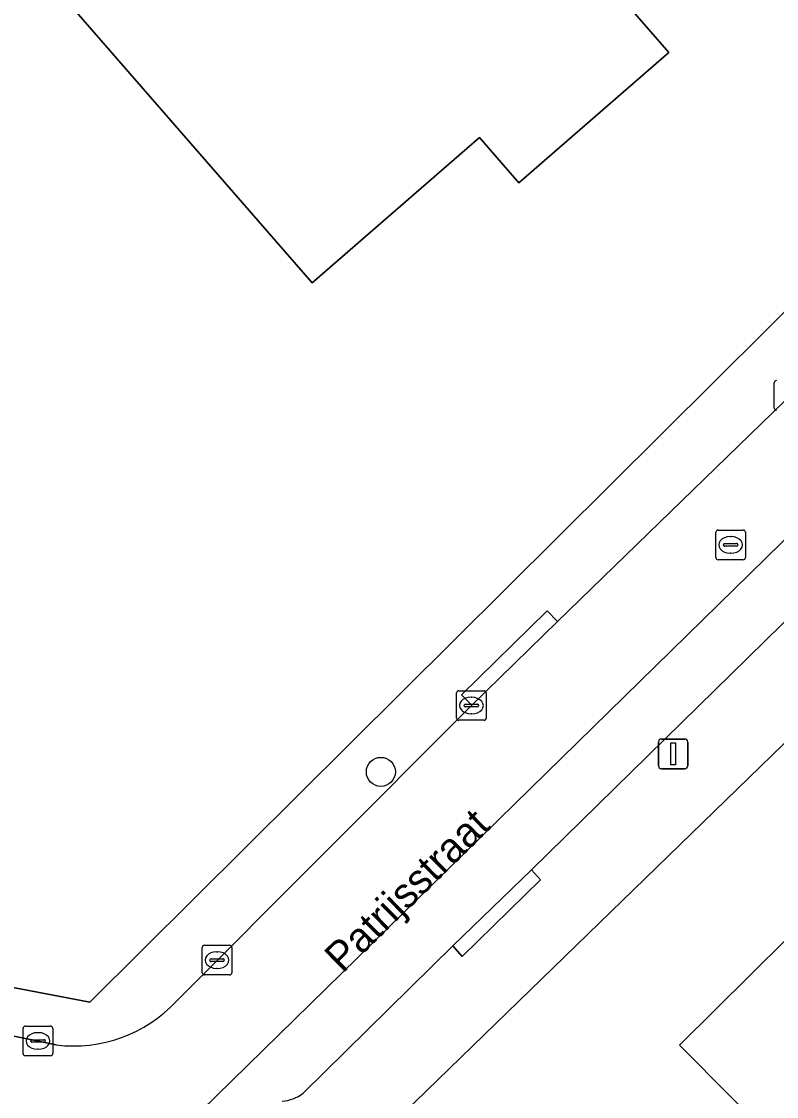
# Model space of a CAD drawing. Extents: x 161772 to 163126, y 383092 to 383917.
# Drawn here: x 162030.56 to 162056.01, y 383362.12 to 383398.39 of the extents above; entities that cross this region are included whole.
import ezdxf

# ---------------------------------------------------------------- set-up
doc = ezdxf.new("R2010")
doc.units = 0
for name, color, linetype in [('IMGEO_Boom', 7, 'Continuous'), ('IMGEO_Erf', 7, 'Continuous'), ('IMGEO_Kolk', 7, 'Continuous'), ('IMGEO_Lichtmast', 7, 'Continuous'), ('IMGEO_Openbare_ruimte_label', 7, 'Continuous'), ('IMGEO_Pand', 7, 'Continuous'), ('IMGEO_Parkeervlak_open', 7, 'Continuous'), ('IMGEO_Rijbaan_lokaal_open', 7, 'Continuous'), ('IMGEO_Rioolput', 7, 'Continuous'), ('IMGEO_Voetpad_gesloten', 7, 'Continuous'), ('IMGEO_Voetpad_open', 7, 'Continuous')]:
    doc.layers.add(name, color=color, linetype=linetype)

msp = doc.modelspace()

# ---------------------------------------------------------------- linework, layer by layer
at = {"layer": 'IMGEO_Boom'}
msp.add_circle((162042.673, 383373.072), 0.489, dxfattribs=at)
at = {"layer": 'IMGEO_Erf'}
for points in [[(161988.831, 383383.094), (161989.798, 383375.666), (161990.795, 383374.566), (161992.579, 383373.341), (161993.75, 383372.87), (162001.33, 383371.327), (162032.857, 383365.301), (162067.97, 383400.221), (162013.474, 383465.049)], [(162056.238, 383360.337), (162052.746, 383363.85), (162057.56, 383368.632)]]:
    msp.add_lwpolyline(points, dxfattribs=at)
for points in [[(162042.442, 383413.304), (162046.279, 383416.509), (162052.35, 383409.242), (162051.959, 383408.915), (162054.742, 383405.585), (162050.598, 383402.122), (162051.674, 383400.885), (162050.321, 383399.709), (162052.378, 383397.343), (162047.321, 383392.948), (162046.001, 383394.468), (162040.357, 383389.564), (162031.415, 383399.854), (162035.794, 383403.659), (162038.856, 383400.136), (162044.666, 383405.185), (162039.757, 383411.061)], [(162085.05, 383335.095), (162085.636, 383334.487), (162109.459, 383358.96), (162108.772, 383359.637), (162097.704, 383370.546), (162075.222, 383392.703), (162064.395, 383381.925), (162038.775, 383357.03), (162035.617, 383357.251), (162035.13, 383353.454), (162066.087, 383323.385), (162066.709, 383324.02), (162059.456, 383331.069), (162065.31, 383337.087), (162065.453, 383336.949), (162072.586, 383330.051), (162076.509, 383326.257)]]:
    msp.add_lwpolyline(points, close=True, dxfattribs=at)
at = {"layer": 'IMGEO_Kolk'}
for p, q in [((162055.936, 383385.344), (162055.936, 383386.196)), ((162045.227, 383374.884), (162045.227, 383375.736)), ((162045.302, 383375.81), (162046.154, 383375.81)), ((162045.715, 383375.59), (162045.74, 383375.59)), ((162046.228, 383375.736), (162046.228, 383374.884)), ((162045.486, 383375.304), (162045.486, 383375.316)), ((162045.924, 383375.267), (162045.526, 383375.267)), ((162045.529, 383375.353), (162045.927, 383375.353)), ((162045.97, 383375.316), (162045.97, 383375.304)), ((162046.154, 383374.81), (162045.302, 383374.81)), ((162045.738, 383375.03), (162045.713, 383375.03)), ((162036.723, 383367.22), (162037.575, 383367.22)), ((162036.648, 383366.294), (162036.648, 383367.146)), ((162037.136, 383367), (162037.161, 383367)), ((162037.649, 383367.146), (162037.649, 383366.294)), ((162036.907, 383366.714), (162036.907, 383366.726)), ((162037.345, 383366.677), (162036.947, 383366.677)), ((162036.95, 383366.763), (162037.348, 383366.763)), ((162037.391, 383366.726), (162037.391, 383366.714)), ((162037.575, 383366.22), (162036.723, 383366.22)), ((162037.159, 383366.44), (162037.134, 383366.44)), ((162030.612, 383363.567), (162030.612, 383364.419)), ((162030.687, 383364.493), (162031.539, 383364.493)), ((162031.613, 383364.419), (162031.613, 383363.567)), ((162030.871, 383363.987), (162030.871, 383363.999)), ((162031.309, 383363.95), (162030.911, 383363.95)), ((162030.914, 383364.036), (162031.312, 383364.036)), ((162031.1, 383364.273), (162031.125, 383364.273)), ((162031.355, 383363.999), (162031.355, 383363.987)), ((162031.123, 383363.713), (162031.098, 383363.713)), ((162031.539, 383363.493), (162030.687, 383363.493))]:
    msp.add_line(p, q, dxfattribs=at)
for points in [[(162055.936, 383385.344), (162055.936, 383386.196)], [(162045.227, 383374.884), (162045.227, 383375.736)], [(162045.302, 383375.81), (162046.154, 383375.81)], [(162046.228, 383375.736), (162046.228, 383374.884)], [(162046.154, 383374.81), (162045.302, 383374.81)], [(162036.723, 383367.22), (162037.575, 383367.22)], [(162036.648, 383366.294), (162036.648, 383367.146)], [(162037.649, 383367.146), (162037.649, 383366.294)], [(162037.575, 383366.22), (162036.723, 383366.22)], [(162030.612, 383363.567), (162030.612, 383364.419)], [(162030.687, 383364.493), (162031.539, 383364.493)], [(162031.613, 383364.419), (162031.613, 383363.567)], [(162031.539, 383363.493), (162030.687, 383363.493)]]:
    msp.add_lwpolyline(points, dxfattribs=at)
for centre, radius, start, end in [((162056.013, 383386.194), 0.0765, 91.552, 178.448), ((162056.013, 383386.194), 0.0765, 91.552, 178.448), ((162056.013, 383385.346), 0.0765, 181.552, 268.448), ((162056.013, 383385.346), 0.0765, 181.552, 268.448), ((162045.304, 383375.734), 0.0765, 91.552, 178.448), ((162045.304, 383375.734), 0.0765, 91.552, 178.448), ((162046.152, 383375.734), 0.0765, 1.552, 88.448), ((162046.152, 383375.734), 0.0765, 1.552, 88.448), ((162045.526, 383375.313), 0.0403, 85.8775, 175.7526), ((162045.523, 383375.303), 0.0366, 178.938, 274.7102), ((162045.927, 383375.31), 0.043, 264.8664, 352.4533), ((162045.931, 383375.315), 0.0386, 1.7309, 96.639), ((162045.304, 383374.886), 0.0765, 181.552, 268.448), ((162045.304, 383374.886), 0.0765, 181.552, 268.448), ((162046.152, 383374.886), 0.0765, 271.552, 358.448), ((162046.152, 383374.886), 0.0765, 271.552, 358.448), ((162036.725, 383367.144), 0.0765, 91.552, 178.448), ((162036.725, 383367.144), 0.0765, 91.552, 178.448), ((162037.573, 383367.144), 0.0765, 1.552, 88.448), ((162037.573, 383367.144), 0.0765, 1.552, 88.448), ((162036.947, 383366.723), 0.0403, 85.8775, 175.7526), ((162036.944, 383366.713), 0.0366, 178.938, 274.7102), ((162037.348, 383366.72), 0.043, 264.8664, 352.4533), ((162037.352, 383366.725), 0.0386, 1.7309, 96.639), ((162036.725, 383366.296), 0.0765, 181.552, 268.448), ((162036.725, 383366.296), 0.0765, 181.552, 268.448), ((162037.573, 383366.296), 0.0765, 271.552, 358.448), ((162037.573, 383366.296), 0.0765, 271.552, 358.448), ((162030.689, 383364.417), 0.0765, 91.552, 178.448), ((162030.689, 383364.417), 0.0765, 91.552, 178.448), ((162031.537, 383364.417), 0.0765, 1.552, 88.448), ((162031.537, 383364.417), 0.0765, 1.552, 88.448), ((162030.911, 383363.996), 0.0403, 85.8775, 175.7526), ((162030.908, 383363.986), 0.0366, 178.938, 274.7102), ((162031.312, 383363.993), 0.043, 264.8664, 352.4533), ((162031.316, 383363.998), 0.0386, 1.7309, 96.639), ((162030.689, 383363.569), 0.0765, 181.552, 268.448), ((162030.689, 383363.569), 0.0765, 181.552, 268.448), ((162031.537, 383363.569), 0.0765, 271.552, 358.448), ((162031.537, 383363.569), 0.0765, 271.552, 358.448)]:
    msp.add_arc(centre, radius, start, end, dxfattribs=at)
for centre, major_axis, ratio, start_param, end_param in [((162045.714, 383375.31), (-0.387, 0.002), 0.722429, 4.712389, 7.853982), ((162045.739, 383375.31), (-0.39, 0.002), 0.717154, 1.570796, 4.712389), ((162037.135, 383366.72), (-0.387, 0.002), 0.722429, 4.712389, 7.853982), ((162037.16, 383366.72), (-0.39, 0.002), 0.717154, 1.570796, 4.712389), ((162031.099, 383363.993), (-0.387, 0.002), 0.722429, 4.712389, 7.853982), ((162031.124, 383363.993), (-0.39, 0.002), 0.717154, 1.570796, 4.712389)]:
    msp.add_ellipse(centre, major_axis=major_axis, ratio=ratio, start_param=start_param, end_param=end_param, dxfattribs=at)
at = {"layer": 'IMGEO_Lichtmast'}
for p, q in [((162052.131, 383374.178), (162052.921, 383374.178)), ((162052.921, 383374.178), (162052.131, 383374.178)), ((162052.031, 383373.278), (162052.031, 383374.078)), ((162052.031, 383374.078), (162052.031, 383373.278)), ((162053.021, 383374.078), (162053.021, 383373.278)), ((162053.021, 383373.278), (162053.021, 383374.078)), ((162052.921, 383373.178), (162052.131, 383373.178)), ((162052.131, 383373.178), (162052.921, 383373.178))]:
    msp.add_line(p, q, dxfattribs=at)
msp.add_lwpolyline([(162052.451, 383374.053), (162052.601, 383374.053), (162052.601, 383373.303), (162052.451, 383373.303), (162052.451, 383374.053)], dxfattribs=at)
for centre, start, end in [((162052.131, 383374.078), 90, 180), ((162052.131, 383374.078), 90, 180), ((162052.921, 383374.078), 0, 90), ((162052.921, 383374.078), 360, 90), ((162052.131, 383373.278), 180, 270), ((162052.131, 383373.278), 180, 270), ((162052.921, 383373.278), 270, 0), ((162052.921, 383373.278), 270, 0)]:
    msp.add_arc(centre, 0.1, start, end, dxfattribs=at)
at = {"layer": 'IMGEO_Pand'}
for points in [[(162044.666, 383405.185), (162038.856, 383400.136), (162035.794, 383403.659), (162031.415, 383399.854), (162040.357, 383389.564), (162046.001, 383394.468), (162047.321, 383392.948), (162052.378, 383397.343), (162050.321, 383399.709), (162051.674, 383400.885), (162050.598, 383402.122), (162054.742, 383405.585), (162051.959, 383408.915), (162052.35, 383409.242), (162046.279, 383416.509), (162042.442, 383413.304), (162039.757, 383411.061)], [(162057.56, 383368.632), (162052.746, 383363.85), (162056.238, 383360.337), (162058.387, 383358.173), (162060.32, 383356.227), (162065.147, 383361.021)]]:
    msp.add_lwpolyline(points, close=True, dxfattribs=at)
at = {"layer": 'IMGEO_Parkeervlak_open'}
for points in [[(162069.402, 383393.751), (162036.595, 383361.608)], [(162040.056, 383362.229), (162045.1, 383367.2), (162047.756, 383369.771), (162068.538, 383390.157)]]:
    msp.add_lwpolyline(points, dxfattribs=at)
msp.add_arc((162039.229, 383363.336), 1.382, 274.7736, 306.7612, dxfattribs=at)
at = {"layer": 'IMGEO_Rijbaan_lokaal_open'}
for points in [[(162070.285, 383399.377), (162069.956, 383398.861), (162069.608, 383398.523), (162048.631, 383378.141), (162045.739, 383375.318), (162035.775, 383365.33)], [(162036.245, 383361.319), (162036.595, 383361.608), (162069.402, 383393.751)], [(162031.731, 383363.861), (162026.624, 383364.907), (162022.901, 383365.67), (161995.201, 383371.459), (161994.524, 383368.077), (162031.651, 383360.514), (162032.009, 383360.453)]]:
    msp.add_lwpolyline(points, dxfattribs=at)
msp.add_arc((162032.317, 383368.548), 4.724, 262.8729, 317.0546, dxfattribs=at)
at = {"layer": 'IMGEO_Rioolput'}
for p, q in [((162053.965, 383380.303), (162053.965, 383381.155)), ((162054.04, 383381.229), (162054.892, 383381.229)), ((162054.453, 383381.009), (162054.478, 383381.009)), ((162054.966, 383381.155), (162054.966, 383380.303)), ((162054.224, 383380.723), (162054.224, 383380.735)), ((162054.662, 383380.686), (162054.264, 383380.686)), ((162054.267, 383380.772), (162054.665, 383380.772)), ((162054.708, 383380.735), (162054.708, 383380.723)), ((162054.476, 383380.449), (162054.451, 383380.449)), ((162054.892, 383380.229), (162054.04, 383380.229))]:
    msp.add_line(p, q, dxfattribs=at)
for points in [[(162053.965, 383380.303), (162053.965, 383381.155)], [(162054.04, 383381.229), (162054.892, 383381.229)], [(162054.966, 383381.155), (162054.966, 383380.303)], [(162054.892, 383380.229), (162054.04, 383380.229)]]:
    msp.add_lwpolyline(points, dxfattribs=at)
for centre, radius, start, end in [((162054.042, 383381.153), 0.0765, 91.552, 178.448), ((162054.042, 383381.153), 0.0765, 91.552, 178.448), ((162054.89, 383381.153), 0.0765, 1.552, 88.448), ((162054.89, 383381.153), 0.0765, 1.552, 88.448), ((162054.264, 383380.732), 0.0403, 85.8775, 175.7526), ((162054.261, 383380.722), 0.0366, 178.938, 274.7102), ((162054.665, 383380.729), 0.043, 264.8664, 352.4533), ((162054.669, 383380.734), 0.0386, 1.7309, 96.639), ((162054.042, 383380.305), 0.0765, 181.552, 268.448), ((162054.042, 383380.305), 0.0765, 181.552, 268.448), ((162054.89, 383380.305), 0.0765, 271.552, 358.448), ((162054.89, 383380.305), 0.0765, 271.552, 358.448)]:
    msp.add_arc(centre, radius, start, end, dxfattribs=at)
for centre, major_axis, ratio, start_param, end_param in [((162054.452, 383380.729), (-0.387, 0.002), 0.722429, 4.712389, 7.853982), ((162054.477, 383380.729), (-0.39, 0.002), 0.717154, 1.570796, 4.712389)]:
    msp.add_ellipse(centre, major_axis=major_axis, ratio=ratio, start_param=start_param, end_param=end_param, dxfattribs=at)
at = {"layer": 'IMGEO_Voetpad_gesloten'}
for points in [[(162069.608, 383398.523), (162067.97, 383400.221), (162032.857, 383365.301), (162001.33, 383371.327), (161993.75, 383372.87), (161992.579, 383373.341), (161990.795, 383374.566), (161989.798, 383375.666), (161989.716, 383372.599), (161995.201, 383371.459), (162022.901, 383365.67), (162023.012, 383366.206), (162026.732, 383365.428), (162026.624, 383364.907), (162031.731, 383363.861)], [(162035.775, 383365.33), (162045.739, 383375.318), (162045.39, 383375.675), (162048.278, 383378.502), (162048.631, 383378.141), (162069.608, 383398.523)], [(162068.538, 383390.157), (162047.756, 383369.771), (162048.059, 383369.433), (162045.418, 383366.844), (162045.1, 383367.2), (162040.056, 383362.229)], [(161990.373, 383368.718), (161989.921, 383365.674), (162000.777, 383363.851), (162008.596, 383362.237), (162022.202, 383359.485), (162028.881, 383358.134), (162029.829, 383357.939), (162030.694, 383357.595), (162035.617, 383357.251), (162038.775, 383357.03), (162064.395, 383381.925)]]:
    msp.add_lwpolyline(points, dxfattribs=at)
for centre, radius, start, end in [((162032.317, 383368.548), 4.724, 262.8729, 317.0546), ((162039.229, 383363.336), 1.382, 274.7736, 306.7612)]:
    msp.add_arc(centre, radius, start, end, dxfattribs=at)
at = {"layer": 'IMGEO_Voetpad_open'}
for points in [[(162048.631, 383378.141), (162048.278, 383378.502), (162045.39, 383375.675), (162045.739, 383375.318)], [(162047.756, 383369.771), (162045.1, 383367.2), (162045.418, 383366.844), (162048.059, 383369.433)]]:
    msp.add_lwpolyline(points, close=True, dxfattribs=at)

# ---------------------------------------------------------------- texts
at = {"layer": 'IMGEO_Openbare_ruimte_label'}
msp.add_text('Patrijsstraat', height=1, rotation=44.5546, dxfattribs=at).set_placement((162041.385, 383366.247))

doc.saveas('drawing.dxf')
